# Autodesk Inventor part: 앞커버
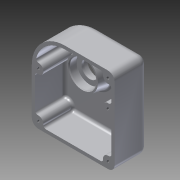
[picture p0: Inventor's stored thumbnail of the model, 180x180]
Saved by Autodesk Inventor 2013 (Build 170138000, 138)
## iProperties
Created: 2015-10
Part Number: 앞커버
Material: 알루미늄 6061
Document SubType Name: Modeling
Designer: mduedu
Density: 2.71 g/cm^3
Mass: 307.08 g
Surface Area: 494.818 cm^2
Volume: 113.314 cm^3
Author: mduedu
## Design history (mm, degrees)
sketch "스케치1"
  geometry: L1 (0, 40)-(60, 40); L2 (60, 40)-(60, -63); L3 (60, -63)-(-40, -63); L4 (-40, -63)-(-40, 0); A1 r 40 centre (0, 0) between (0, 40) and (-40, 0); 1 further point
  constraints: 8 end point, 2 point on circle, 2 tangent, 1 centre point, 1 coincident, 1 horizontal, 1 parallel, 1 perpendicular, 1 vertical
  dimensions: "d0" = 40 radius of A1; "d1" = 103 distance of L1.end L2.end; "d2" = 100 distance of L2.end L3.end
extrude "돌출2" new body sketch "스케치1" distance "d8" = 40; taper "d9" = 0 deg
fillet "모깎기3" dims "d10" = 8
fillet "모깎기4" dims "d11" = 8
feature "쉘2" dims "d12" = 4
sketch "스케치2"
  geometry: C1 r 21.5 at (32, 55); 1 further point
  constraints: 1 centre point, 1 coincident
  dimensions: "d13" = 43 diameter of C1
extrude "돌출3" join sketch "스케치2" distance "d14" = 15; taper "d15" = 0 deg
hole "구멍1" diameter "d18" = 32; stored, may be unused: countersink angle "d22" = 90 deg, drill point angle "d24" = 0 deg; dims "d16" = 10, "d17" = 10, "d19" = 6, "d20" = 4, "d21" = 2, "d23" = 9
hole "구멍2" diameter "d27" = 20; stored, may be unused: countersink angle "d31" = 90 deg, drill point angle "d33" = 0 deg; dims "d25" = 10, "d26" = 10, "d28" = 6, "d29" = 4, "d30" = 2, "d32" = 3
hole "구멍3" diameter "d36" = 25; stored, may be unused: countersink angle "d40" = 90 deg, drill point angle "d42" = 0 deg; dims "d34" = 10, "d35" = 10, "d37" = 6, "d38" = 4, "d39" = 2, "d41" = 3
chamfer "모따기1" distance "d43" = 1; stored, may be unused: second distance "d44" = 2, angle "d45" = 45 deg
feature "면 기울기1" dims angle "d46" = 10 deg
sketch "스케치3"
  geometry: L1 (-40, 0)-(-40, -55) reference; L2 (60, -55)-(60, 32) reference; L3 (-40, 0)-(60, 0); C1 r 6 at (52, 32); C2 r 6 at (52, -55); C3 r 6 at (-32, -55); C4 r 6 at (52, 0); C5 r 6 at (-32, 0); A1 r 8 centre (52, 32) between (60, 32) and (52, 40) reference; A2 r 8 centre (52, -55) between (52, -63) and (60, -55) reference; A3 r 8 centre (-32, -55) between (-40, -55) and (-32, -63) reference; 1 further point
  constraints: 5 centre point, 4 equal radius, 3 coincident, 3 point on line, 2 end point, 2 vertical alignment, 1 perpendicular
  dimensions: "d47" = 6 radius of C1
extrude "돌출4" join sketch "스케치3" stored distance "d49" = 15; taper "d50" = 0 deg
fillet "모깎기5" dims "d51" = 3
fillet "모깎기6" dims "d52" = 3
sketch "스케치4"
  geometry: A1 r 6 centre (-32, 0) between (-32.667, -5.963) and (-31.833, 5.998) reference; A2 r 6 centre (52, 32) between (46.037, 32.667) and (52.667, 26.037) reference; A3 r 6 centre (52, 0) between (52.667, 5.963) and (52.667, -5.963) reference; A4 r 6 centre (52, -55) between (52.667, -49.037) and (46.037, -55.667) reference; A5 r 6 centre (-32, -55) between (-26.037, -55.667) and (-32.667, -49.037) reference; 6 further points
  constraints: 5 coincident
hole "구멍4" sketch "스케치4" at (-32, 0), (52, 32), (52, 0), (52, -55), (-32, -55) diameter "d53" = 3.242; stored, may be unused: countersink angle "d57" = 90 deg, drill point angle "d59" = 118 deg; dims "d54" = 12, "d55" = 4, "d56" = 2, "d58" = 14
sketch "스케치5"
  geometry: L1 (-52, -63)-(32, -63) reference; L2 (-60, 32)-(-60, -55) reference; 2 further points
  constraints: 1 other
  dimensions: "d60" = 20 distance from line of point (-10, -43) L1; "d61" = 50 distance from line of point (-10, -43) L2
feature "엠보싱1" sketch "스케치5" dims "d13" = 43, "d62" = 0.5, "d63" = 0
fillet "모깎기7" dims "d64" = 0.3
sketch "스케치6"
  geometry: L1 (-52, -55)-(-52, 32) reference; L2 (32, -55)-(-52, -55) reference; L3 (32, 0)-(32, -55) reference; L4 (-52, 32)-(0, 32) reference; L5 (8.016, -42.735)-(8.016, -44.307) reference; L6 (11.598, -44.062)-(11.655, -44.51) reference; L7 (7.479, -44.787)-(7.479, -40.431) reference; L8 (7.479, -40.431)-(10.955, -40.431) reference; L9 (10.955, -40.431)-(10.955, -40.879) reference; L10 (10.955, -40.879)-(8.016, -40.879) reference; L11 (8.016, -40.879)-(8.016, -42.288) reference; L12 (8.016, -42.288)-(10.638, -42.288) reference; L13 (10.638, -42.288)-(10.638, -42.735) reference; L14 (10.638, -42.735)-(8.016, -42.735) reference; L15 (4.939, -39.748)-(4.939, -44.999) reference; L16 (4.939, -44.999)-(4.393, -44.999) reference; L17 (4.393, -44.999)-(4.393, -39.495) reference; L18 (4.393, -39.495)-(4.825, -39.495) reference; L19 (3.547, -39.87)-(3.547, -44.697) reference; L20 (3.547, -44.697)-(3.001, -44.697) reference; L21 (3.001, -44.697)-(3.001, -41.791) reference; L22 (3.001, -41.791)-(1.764, -41.791) reference; L23 (1.764, -41.791)-(1.764, -41.376) reference; L24 (1.764, -41.376)-(3.001, -41.376) reference; L25 (3.001, -41.376)-(3.001, -39.585) reference; L26 (3.001, -39.585)-(3.449, -39.585) reference; L27 (5.11, -46.155)-(5.11, -46.602) reference; L28 (5.11, -46.602)-(-0.076, -46.602) reference; L29 (-0.076, -46.602)-(-0.076, -44.307) reference; L30 (-0.076, -44.307)-(0.323, -44.307) reference; L31 (0.461, -44.551)-(0.461, -46.155) reference; L32 (0.461, -46.155)-(5.11, -46.155) reference; L33 (2.497, -43.297)-(2.13, -43.712) reference; L34 (-1.102, -43.957)-(-1.476, -43.55) reference; L35 (0.404, -39.813)-(0.885, -39.813) reference; L36 (-2.763, -44.176)-(-2.225, -44.176) reference; L37 (-2.274, -41.889)-(-2.82, -41.889) reference; L38 (-8.168, -40.138)-(-8.168, -40.635) reference; L39 (-8.168, -40.635)-(-10.041, -40.635) reference; L40 (-10.041, -40.635)-(-10.041, -46.138) reference; L41 (-10.041, -46.138)-(-10.586, -46.138) reference; L42 (-10.586, -46.138)-(-10.586, -40.635) reference; L43 (-10.586, -40.635)-(-12.45, -40.635) reference; L44 (-12.45, -40.635)-(-12.45, -40.138) reference; L45 (-12.45, -40.138)-(-8.168, -40.138) reference; L46 (-22.114, -44.022)-(-19.94, -44.022) reference; L47 (-19.94, -44.022)-(-19.94, -46.57) reference; L48 (-19.94, -46.57)-(-20.494, -46.57) reference; L49 (-20.494, -46.57)-(-20.494, -44.469) reference; L50 (-20.494, -44.469)-(-25.094, -44.469) reference; L51 (-25.094, -44.469)-(-25.094, -44.022) reference; L52 (-25.094, -44.022)-(-22.659, -44.022) reference; L53 (-22.659, -44.022)-(-22.659, -42.556) reference; L54 (-22.659, -42.556)-(-25.973, -42.556) reference; L55 (-25.973, -42.556)-(-25.973, -42.109) reference; L56 (-25.973, -42.109)-(-20.73, -42.109) reference; L57 (-20.388, -40.106)-(-24.955, -40.106) reference; L58 (-24.955, -40.106)-(-24.955, -39.65) reference; L59 (-24.955, -39.65)-(-19.81, -39.65) reference; L60 (-20.136, -42.109)-(-18.768, -42.109) reference; L61 (-18.768, -42.109)-(-18.768, -42.556) reference; L62 (-18.768, -42.556)-(-22.114, -42.556) reference; L63 (-22.114, -42.556)-(-22.114, -44.022) reference; L64 (-13.501, -46.138)-(-14.168, -44.307) reference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; C1 r 13.5 at (0, 0) reference; A1 r 32 centre (0, 0) between (32, 0) and (0, 32) reference; 53 further points
  constraints: 68 other
node "솔리드2"
